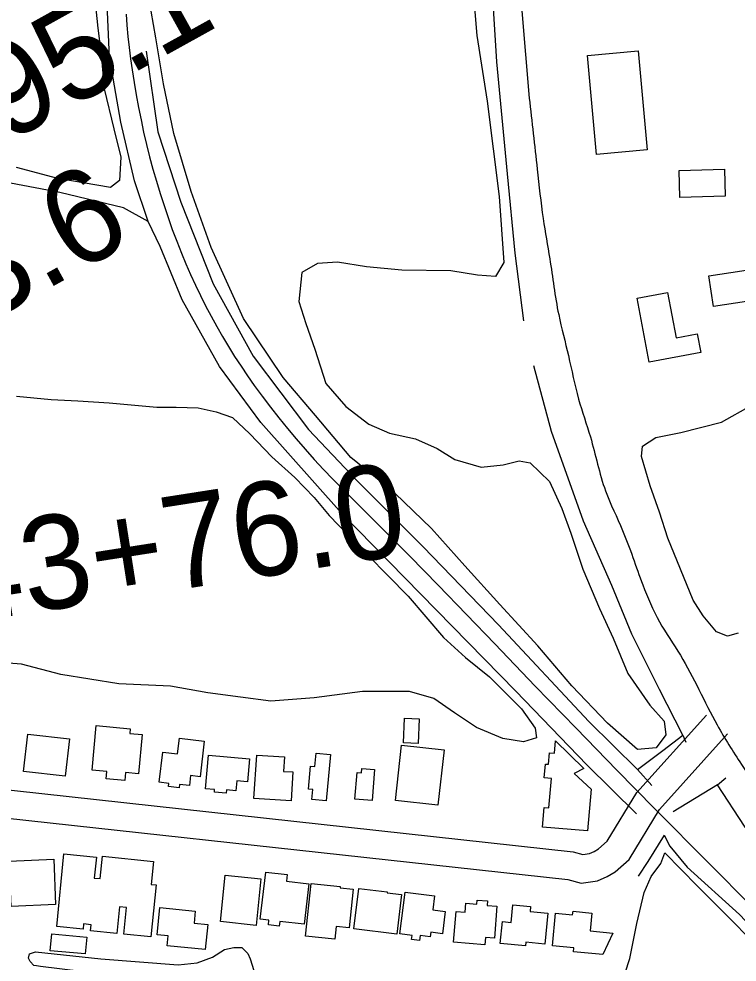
# Model space of a CAD drawing. Extents: x 3715084 to 3753216, y 488173 to 513963.
# Drawn here: x 3736010 to 3736776, y 501479 to 502484 of the extents above; entities that cross this region are included whole.
import ezdxf

# ---------------------------------------------------------------- set-up
doc = ezdxf.new("R2010")
doc.units = 0
for name, color, linetype in [('V-BLDG-OTLN', 7, 'Continuous'), ('V-RAIL-TRAK', 7, 'Continuous'), ('V-ROAD-CNTR', 7, 'Continuous'), ('V-SITE-VEGE', 7, 'Continuous'), ('V-SURV-IDEN', 7, 'Continuous'), ('V-TOPO-SHOR', 7, 'Continuous')]:
    doc.layers.add(name, color=color, linetype=linetype)

msp = doc.modelspace()

# ---------------------------------------------------------------- linework, layer by layer
at = {"layer": 'V-BLDG-OTLN'}
for points in [[(3736626.2, 502339.9), (3736616.6, 502445.5), (3736670.7, 502450.5), (3736680.3, 502344.9)], [(3736763.3, 502295.5), (3736715, 502294.2), (3736714.3, 502322.9), (3736762.6, 502324.1)], [(3736745.9, 502210.5), (3736809, 502220.1), (3736814, 502187.6), (3736750.9, 502178)], [(3736682.1, 502118.4), (3736669.3, 502186.7), (3736701.8, 502192.8), (3736710.9, 502144.3), (3736733.5, 502148.6), (3736737.2, 502128.8)], [(3736437.2, 501738.2), (3736435.9, 501711.8), (3736420.3, 501712.6), (3736421.6, 501739)], [(3736141.7, 501721.6), (3736137.8, 501679.7), (3736124.1, 501681), (3736123.3, 501672.4), (3736103.4, 501674.2), (3736104.1, 501682.1), (3736088.4, 501683.6), (3736092.8, 501731), (3736129.1, 501727.6), (3736128.7, 501722.8)], [(3736064.4, 501717.1), (3736059.9, 501677.2), (3736015.4, 501682.2), (3736019.9, 501722.1)], [(3736208, 501714.5), (3736203.5, 501676.5), (3736193.5, 501677.7), (3736192.3, 501667.1), (3736181.7, 501668.4), (3736181.3, 501664.7), (3736169.9, 501666.1), (3736170.3, 501669.4), (3736160, 501670.6), (3736163.8, 501702.9), (3736179.6, 501701), (3736181.5, 501717.6)], [(3736463.6, 501705.4), (3736457.1, 501646.1), (3736411.8, 501651.1), (3736418.2, 501710.3)], [(3736620.5, 501663.2), (3736616.6, 501618.7), (3736568.7, 501622.9), (3736570.5, 501643.8), (3736575.4, 501643.4), (3736578.1, 501674.8), (3736570.5, 501675.4), (3736571.8, 501690.1), (3736574.9, 501689.9), (3736575.9, 501702.2), (3736581.3, 501701.7), (3736582.4, 501714.8), (3736612.8, 501685.5), (3736602.4, 501680)], [(3736212.5, 501699.7), (3736256.3, 501695.8), (3736254.1, 501671), (3736242.7, 501672), (3736241.8, 501661.6), (3736231.7, 501662.5), (3736231.4, 501659), (3736218.8, 501660.1), (3736219, 501663), (3736209.3, 501663.8)], [(3736302.6, 501681.6), (3736300.7, 501650.7), (3736260.9, 501653.2), (3736263.9, 501699.5), (3736293.6, 501697.6), (3736292.6, 501682.2)], [(3736342.5, 501700.3), (3736338, 501650.7), (3736322.7, 501652.1), (3736323.7, 501662.8), (3736319.1, 501663.2), (3736321.4, 501687.8), (3736325.9, 501687.4), (3736327.2, 501701.7)], [(3736389.5, 501684.2), (3736387, 501651.3), (3736368.6, 501652.8), (3736370.9, 501681.1), (3736375.8, 501680.7), (3736376.1, 501685.2)], [(3736047.6, 501588.5), (3736049.5, 501540.2), (3736002.1, 501538.3), (3736000.2, 501586.6)], [(3736050.8, 501517), (3736058.5, 501594.3), (3736093, 501590.8), (3736090.8, 501568.5), (3736097.2, 501567.9), (3736099.6, 501591.7), (3736153.9, 501586.2), (3736151.4, 501561.8), (3736156.7, 501561.2), (3736151.2, 501505.8), (3736122.4, 501508.7), (3736125.2, 501537.3), (3736117.8, 501538), (3736114.9, 501509.5), (3736086.7, 501512.4), (3736087.3, 501518.8), (3736079.4, 501519.6), (3736078.9, 501514.2)], [(3736267.7, 501524.7), (3736273.6, 501574.9), (3736296.5, 501572.2), (3736295.7, 501565.1), (3736319.4, 501562.4), (3736314.4, 501519.2), (3736288.4, 501522.2), (3736287.8, 501517.3), (3736276.4, 501518.7), (3736277, 501523.6)], [(3736225.3, 501522.1), (3736230.4, 501571.7), (3736268.4, 501567.7), (3736263.2, 501518.1)], [(3736316, 501506.6), (3736321.8, 501562.6), (3736352.9, 501559.4), (3736352.8, 501558.1), (3736366.6, 501556.7), (3736362.4, 501515.5), (3736348.6, 501516.9), (3736347.2, 501503.4)], [(3736367.5, 501514.3), (3736372.7, 501557.5), (3736403.1, 501553.8), (3736403, 501552.9), (3736418.4, 501551.1), (3736413.3, 501508.8)], [(3736416.5, 501509.1), (3736422.3, 501553.6), (3736453.4, 501549.5), (3736451.5, 501534.8), (3736464.9, 501533), (3736461.8, 501509.2), (3736449.5, 501510.8), (3736448.9, 501505.9), (3736438.1, 501507.3), (3736437.4, 501501.9), (3736429, 501503), (3736429.6, 501507.4)], [(3736473.8, 501500.1), (3736476.4, 501532.9), (3736486, 501532.2), (3736486.8, 501541.6), (3736498.5, 501540.7), (3736498.9, 501544.9), (3736510.1, 501544.1), (3736509.7, 501539.3), (3736520, 501538.5), (3736517.3, 501504.6), (3736507.9, 501505.3), (3736507.2, 501497.5)], [(3736209.1, 501492.5), (3736168.6, 501496.4), (3736169.6, 501506.8), (3736157.8, 501507.9), (3736160.5, 501537), (3736198.3, 501533.4), (3736197.1, 501520.4), (3736211.7, 501519)], [(3736574.2, 501531), (3736571, 501498.1), (3736550.7, 501500.1), (3736550.3, 501496.2), (3736523.5, 501498.8), (3736525.8, 501522.2), (3736535.1, 501521.3), (3736536.9, 501540.1), (3736555.9, 501538.2), (3736555.4, 501532.8)], [(3736579.4, 501496.2), (3736582.6, 501531), (3736600.7, 501529.3), (3736601.1, 501533.1), (3736621, 501531.2), (3736619.3, 501512.1), (3736643.4, 501509.8), (3736633, 501487), (3736601.6, 501489.9), (3736601.9, 501494.1)], [(3736045.4, 501508.9), (3736082.8, 501505.6), (3736081.2, 501487.7), (3736043.9, 501490.9)]]:
    msp.add_lwpolyline(points, close=True, dxfattribs=at)
at = {"layer": 'V-RAIL-TRAK'}
for points in [[(3736124.7, 502489.6), (3736125.6, 502477.7), (3736126.7, 502465.8), (3736128, 502453.9), (3736129.5, 502442), (3736131.2, 502430.1), (3736133.2, 502416.8), (3736135.5, 502403.4)], [(3736135.5, 502403.4), (3736137.9, 502390.1), (3736140.6, 502376.9), (3736143.4, 502363.7), (3736146.5, 502350.5), (3736149.8, 502337.4), (3736153.3, 502324.4), (3736157, 502311.4), (3736160.9, 502298.4), (3736165.1, 502285.6), (3736169.4, 502272.8), (3736173.9, 502260), (3736178.7, 502247.4), (3736183.6, 502234.8), (3736188.4, 502223.3), (3736193.4, 502212), (3736198.5, 502200.7), (3736203.9, 502189.5), (3736209.5, 502178.5), (3736215.3, 502167.5), (3736221.3, 502156.6), (3736227.5, 502145.9), (3736233.9, 502135.2), (3736240.4, 502124.7), (3736247.2, 502114.3), (3736254.1, 502104), (3736261.3, 502093.8), (3736269.9, 502082.1), (3736278.6, 502070.5), (3736287.6, 502059.1), (3736296.7, 502047.8)], [(3736296.7, 502047.8), (3736306, 502036.7), (3736315.5, 502025.7), (3736325.2, 502014.9), (3736335, 502004.2), (3736345, 501993.6), (3736355.2, 501983.3), (3736365.5, 501973.1), (3736396.4, 501942.5), (3736427, 501911.7), (3736457.5, 501880.7), (3736487.7, 501849.5), (3736517.8, 501818.2), (3736560.9, 501773.1), (3736604.3, 501728.3), (3736647.8, 501683.7), (3736688, 501642.8), (3736691.5, 501639.2), (3736794.5, 501535.5)]]:
    msp.add_lwpolyline(points, dxfattribs=at)
at = {"layer": 'V-ROAD-CNTR'}
for points in [[(3736184.7, 506906.1), (3736197, 506766.8), (3736212.8, 506567.9), (3736232.6, 506284.2), (3736257.8, 505993.5), (3736279.1, 505753.5), (3736349.3, 504920.1), (3736384.6, 504480.2), (3736421.9, 504020), (3736483.8, 503285.7), (3736534.1, 502641.5), (3736554.4, 502400)], [(3735795, 501684.8), (3736601.2, 501596.6), (3736611.7, 501593.7), (3736618.8, 501594.8), (3736623.7, 501596.9), (3736628.3, 501599.6), (3736637.5, 501607.8), (3736669.2, 501659.7), (3736743.4, 501742.2)], [(3735803.2, 501653.7), (3736595.6, 501567), (3736609.8, 501563.1), (3736627.3, 501565.7), (3736637.4, 501570.2), (3736646.1, 501575.3), (3736660.8, 501588.4), (3736693.4, 501641.7), (3736765.7, 501722.2)]]:
    msp.add_lwpolyline(points, dxfattribs=at)
msp.add_spline([(3736554.4, 502400), (3736562.9, 502324.3), (3736569.3, 502271.5), (3736576.3, 502228.7), (3736585.8, 502169.2), (3736596.2, 502125.5), (3736607, 502079.2), (3736619.6, 502038.8), (3736635.8, 501981.2), (3736653.9, 501939.2), (3736675.4, 501881.2), (3736693.2, 501841.7), (3736715.5, 501806.1), (3736735.3, 501769.5), (3736754.8, 501731.7), (3736780.6, 501689.7), (3736803.6, 501655.2), (3736832.2, 501615.9), (3736869.3, 501570.8)], degree=3, dxfattribs=at)
at = {"layer": 'V-SITE-VEGE'}
for points in [[(3736492.3, 502543), (3736498.5, 502466.7), (3736509.5, 502396.6), (3736522.5, 502295), (3736527.3, 502224.9), (3736518.3, 502209.8), (3736499.1, 502211.2), (3736470.9, 502216), (3736418.7, 502216.7), (3736380.9, 502220.1), (3736350, 502225), (3736328.7, 502223.6), (3736312.2, 502214), (3736308.8, 502183.1), (3736316.3, 502159.7), (3736325.9, 502132.2), (3736337.6, 502095.8), (3736358.9, 502071.1), (3736383.6, 502052.5), (3736405.6, 502042.9), (3736433.1, 502036.7), (3736456.4, 502026.4), (3736475, 502014.7), (3736503.1, 502006.4), (3736526.5, 502009.2), (3736543.7, 502013.3), (3736555.3, 502011.2), (3736576, 501991.3), (3736589, 501962.4), (3736598.6, 501936.3), (3736611.6, 501897.9), (3736629.5, 501855.9), (3736643.9, 501824.3), (3736659.7, 501786.5), (3736683, 501752.9), (3736698.1, 501735.7), (3736700.2, 501721.3), (3736689.9, 501707.5), (3736670, 501705.5), (3736637.7, 501733.7), (3736599.9, 501773.5), (3736563.5, 501816.1), (3736523, 501860.1), (3736485.9, 501901.3), (3736450.2, 501941.2), (3736411.1, 501979), (3736364.4, 502016.8), (3736326.6, 502061.5), (3736292.3, 502102), (3736249.7, 502165.2), (3736215.4, 502240.8), (3736194.1, 502300.6), (3736175.6, 502362.4), (3736164.6, 502415.3), (3736156.4, 502464.1), (3736148.8, 502507.4)], [(3736090.4, 502516.3), (3736094.5, 502474.4), (3736098, 502446.9), (3736101.4, 502409.8), (3736111.7, 502367.2), (3736119.2, 502337), (3736117.8, 502312.3), (3736108.2, 502304.7), (3736051.9, 502314.4), (3736007.9, 502326.1)], [(3736007.8, 502082.2), (3736044.9, 502078.7), (3736073.1, 502077.4), (3736106.8, 502075.3), (3736157.6, 502070.5), (3736178.2, 502070.4), (3736201.6, 502069.7), (3736220.8, 502065.6), (3736238, 502059.4), (3736256.5, 502042.2), (3736279.9, 502017.5), (3736304.6, 501995.5), (3736325.2, 501974.2), (3736341, 501955), (3736360.9, 501934.4), (3736425.5, 501869.1), (3736463.2, 501825.1), (3736486.6, 501803.8), (3736512, 501783.2), (3736546.3, 501748.8), (3736560.7, 501728.2), (3736562.1, 501717.9), (3736548.4, 501713.8), (3736526.4, 501717.2), (3736498.2, 501728.9), (3736474.9, 501744.7), (3736452.9, 501759.8), (3736426.8, 501767.4), (3736376.6, 501767.4), (3736325.1, 501760.6), (3736279.1, 501757.1), (3736246.8, 501761.3), (3736211.8, 501766.1), (3736171.9, 501773), (3736117, 501775.7), (3736055.1, 501785.4), (3736013.2, 501796.4), (3735961.7, 501800.5)], [(3736777.3, 501829.5), (3736765.7, 501826.4), (3736754.2, 501831.1), (3736740, 501847.9), (3736729, 501864.7), (3736702.3, 501930.7), (3736693.4, 501958.5), (3736683.5, 501986.8), (3736674.1, 502017.8), (3736675.1, 502028.8), (3736689.3, 502038.2), (3736716, 502043.4), (3736759.5, 502054.4), (3736791, 502072.2)], [(3736641.7, 501421.8), (3736661.6, 501482.9), (3736669.2, 501520), (3736676.8, 501553), (3736684.3, 501570.1), (3736694.6, 501583.9), (3736698.8, 501595.5), (3736733.8, 501559.8), (3736767.5, 501526.1), (3736791.5, 501502.1)]]:
    msp.add_lwpolyline(points, dxfattribs=at)
msp.add_lwpolyline([(3736033.3, 501474.3), (3736029.3, 501474.9), (3736026.4, 501475.4), (3736022.3, 501479.5), (3736020.6, 501483), (3736021.7, 501487.6), (3736028.1, 501489.9), (3736097.8, 501482.4), (3736180.2, 501476), (3736200.5, 501478.3), (3736216.7, 501484.1), (3736229.5, 501492.2), (3736239.4, 501494.5), (3736248.1, 501494.5), (3736254.4, 501488.1), (3736256.8, 501482.3), (3736260.8, 501470.1), (3736270.7, 501464.3), (3736274.7, 501458.5), (3736275.3, 501451.6), (3736274.2, 501448.1), (3736189.4, 501455.1)], close=True, dxfattribs=at)
at = {"layer": 'V-TOPO-SHOR'}
msp.add_line((3736755.1, 501667.9), (3736707.7, 501639.1), dxfattribs=at)
for points in [[(3736148.1, 502268.6), (3736133.6, 502311.9), (3736119.2, 502374.4), (3736106.9, 502443.8), (3736103.5, 502524.2), (3736108.3, 502605.2), (3736123.5, 502711.7), (3736144.8, 502788), (3736177.1, 502863.5), (3736209.4, 502952.8), (3736237.6, 503025.6), (3736265.1, 503084), (3736289.9, 503144.4), (3736304.3, 503205.6), (3736318.1, 503267.4), (3736331.2, 503330.6)], [(3736548.5, 502162.6), (3736539.6, 502234.8), (3736531.4, 502319.3), (3736519.8, 502438.8), (3736513.6, 502541.9), (3736507.5, 502630.5), (3736494.5, 502750.7), (3736486.3, 502847.6), (3736476.7, 502928), (3736471.9, 503041.3), (3736465.1, 503138.9)], [(3736146.1, 502449.9), (3736158.4, 502364.1), (3736183.1, 502289.2), (3736217.4, 502201.9), (3736260, 502125), (3736319, 502046.6), (3736370.5, 501992.3), (3736441.3, 501921.5), (3736521.6, 501838.4), (3736617.8, 501735.3), (3736670, 501684.4), (3736685.1, 501667.3)], [(3736668.6, 501637), (3736615.7, 501689.3), (3736540.1, 501767.6), (3736455.7, 501854.2), (3736354.7, 501957.3), (3736268.2, 502054.2), (3736224.3, 502114), (3736184.4, 502184.8), (3736161.1, 502241.8), (3736148.1, 502268.6), (3736122, 502283), (3736054, 502299.5), (3735954.3, 502318.1), (3735863, 502329.8), (3735828.6, 502335.3), (3735766.8, 502345), (3735674.1, 502346.4), (3735633.5, 502347.8), (3735593, 502339.5), (3735575.8, 502340.2), (3735532.5, 502350.6)], [(3736718.1, 501720.8), (3736693.3, 501769.6), (3736663.8, 501828.7), (3736642.5, 501880.3), (3736612.3, 501949), (3736578, 502044.5), (3736559.5, 502114.5)], [(3736670, 501684.4), (3736696.8, 501704.4), (3736718.1, 501720.8), (3736721.5, 501713.3)], [(3737438.6, 500922.8), (3737415.8, 500947), (3737323, 501039.1), (3737258.5, 501103.7), (3737156.2, 501210.9), (3737058, 501311.3), (3736955.6, 501415.7), (3736862.9, 501515.4), (3736784, 501624), (3736755.1, 501667.9), (3736764.1, 501675.5)], [(3736698.1, 501614.4), (3736680.9, 501586.2), (3736670.6, 501570.4)], [(3736698.1, 501614.4), (3736704.3, 501602.7), (3736722.8, 501580), (3736778.4, 501529.8), (3736857.4, 501446), (3736947.4, 501356.7), (3737042.8, 501256.3), (3737115.6, 501186.2), (3737201.5, 501094.8), (3737284.6, 501006.9), (3737367, 500925.1), (3737434.3, 500852.2), (3737506.4, 500781.4)]]:
    msp.add_lwpolyline(points, dxfattribs=at)

# ---------------------------------------------------------------- texts
at = {"layer": 'V-SURV-IDEN'}
for s, rotation, p in [('538+95.1', 29.0083, (3735733.8, 502205.3)), ('540+23.6', 28.9867, (3735643.3, 501975.8)), ('543+76.0', 8.8788, (3735873.4, 501827.8))]:
    msp.add_text(s, height=100, rotation=rotation, dxfattribs=at).set_placement(p)

doc.saveas('drawing.dxf')
